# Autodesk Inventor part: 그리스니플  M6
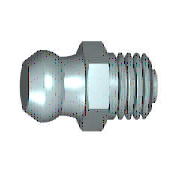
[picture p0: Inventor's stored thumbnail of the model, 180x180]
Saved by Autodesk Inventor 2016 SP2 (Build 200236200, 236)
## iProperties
IsCustomPart: 1
Created: 2012-02
Part Number: 그리스니플  M6
Material: 강철, 연강
Description: 그리스 니플에 대한 사양. 제I부: 버튼 머리 그리스 니플 유형 A
Document SubType Name: Modeling
Standard: IS 4009
Designer: mduedu
Standards Organization: IS
Language: ko-KR
Size Designation: M6 원추 짧은
Categories: <MemberInstance><Categories><Category DisplayName="기타 부품" InternalName="5aa15e00-363f-49f2-933f-16f664388e3f" Mnemonic="OTHER"><Category DisplayName="그리스 부속품" I
Density: 1 g/cm^3
Appearance: 강철
Author: mduedu
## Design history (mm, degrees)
sketch "스케치1"
  geometry: L1 (-9.8, 0)-(-9.8, 2.25); L2 (-9.8, 2.25)-(-8.055, 3.194); L3 (-9.8, 0)-(6.2, 0); L4 (6.2, 0)-(6.2, 1.5); L5 (6.2, 1.5)-(5.5, 1.5); L6 (5.5, 1.5)-(5.5, 3); L7 (5.5, 3)-(0, 3); L8 (-13, 0)-(9.4, 0) reference; L9 (0, -1.725)-(0, 10.35) reference; L10 (-3, 3.5)-(0, 3.5); L11 (0, 3.5)-(0, 3); A1 r 3.25 centre (-7.455, 0) between (-5.573, 2.65) and (-8.055, 3.194); A2 r 6 centre (-6.12, 8.625) between (-5.573, 2.65) and (-3, 3.5)
  constraints: 18 end point, 5 perpendicular, 4 point on circle, 2 centre point, 2 parallel, 2 point on line, 1 collinear, 1 vertical
  dimensions: "d0" = 16 distance between parallel lines of L1 L4 (= GL); "d1" = 5.3 diameter of A1.start L3 (= KGB2); "d2" = 0.7 distance between parallel lines of L4 L6 (= PHH); "d3" = 3 diameter of L5 L3 (= 0.5 x NND); "d4" = 6 diameter of L7 L3 (= NND); "d5" = 6.5 dimension on A1 L3 (= KR); "d6" = 4.5 diameter of L1.end L3 (= KGB1); "d7" = 6 radius of A2 (= RBN); "d11" = 7 diameter of L10.start L3 (= SW); "d14" = 3 distance of L10.start L10.end (= KOH); "d15" = 5.5 distance between parallel lines of L6 L11 (= NLG); "d61" = 8.05479 distance from line of L9 L2.end (computed from KGB1, KR, PHH, GL, NLG, VERS); "d62" = 7.45479 distance from line of L9 A1.centre (computed from NLG, GL, PHH, KR, KGB1)
revolve "본체" sketch "스케치1" stored, may be unused: angle "d25" = 90 deg
sketch "스케치2"
  geometry: L1 (2.021, 3.5)-(4.041, 0); L2 (4.041, 0)-(2.021, -3.5); L3 (2.021, -3.5)-(-2.021, -3.5); L4 (-2.021, -3.5)-(-4.041, 0); L5 (-4.041, 0)-(-2.021, 3.5); L6 (-2.021, 3.5)-(2.021, 3.5); C1 r 3.5 at (0, 0) reference; 1 further point
  constraints: 12 end point, 1 coincident, 1 horizontal, 1 tangent, 11 other
extrude "머리" join sketch "스케치2" distance "d17" = 3 (= KOH); taper "d18" = 0 deg
sketch "스케치3"
  geometry: L1 (2.687, 4.041)-(3, 4.041); L2 (3, 4.041)-(3, 3.5); L3 (3, 3.5)-(2.687, 4.041); L4 (0.313, 4.041)-(0, 4.041); L5 (0, 4.041)-(0, 3.5); L6 (0, 3.5)-(0.313, 4.041); L7 (3.6, 0)-(-0.6, 0) reference; L8 (0, 4.041)-(0, 2.021) reference; L9 (0, 4.041)-(3, 4.041) reference; L10 (3, 3.031)-(3, 4.041) reference
  constraints: 12 end point, 4 collinear, 3 perpendicular, 1 horizontal
  dimensions: "d19" = 3.5 distance from line of L5.end L7 (= 0.5 x SW); "d20" = 3.5 distance from line of L2.end L7 (= 0.5 x SW); "d21" = 30 deg angle of L6 L5; "d22" = 30 deg angle of L2 L3
revolve "모따기1" sketch "스케치3" stored, may be unused: angle "d56" = 90 deg
body "Solid1"
fillet "모깎기1" dims "d8" = 0.2 (= RR)
feature "스레드1" dims "d9" = 4.88655 (= NLG - GAL), "d10" = 0
chamfer "모따기2" distance "d23" = 0.61345 (= -0.5 x GD1 + 0.5 x NND); stored, may be unused: angle "d24" = 45 deg, second distance "d59" = 0.61345 (= -0.5 x GD1 + 0.5 x NND)
other parameters: "NLG" = 5.5 [user parameter; used in 4 equation terms], "GL" = 16 [user parameter; used in 3 equation terms], "NND" = 6 [user parameter; used in 4 equation terms], "KGB1" = 4.5 [user parameter; used in 3 equation terms], "KGB2" = 5.3 [user parameter; used in 1 equation term], "VERS" = 0.6 [user parameter; used in 1 equation term], "KR" = 6.5 [user parameter; used in 3 equation terms], "RBN" = 6 [user parameter; used in 1 equation term], "SW" = 7 [user parameter; used in 3 equation terms], "KOH" = 3 [user parameter; used in 2 equation terms], "GAL" = 0.61345 (= 0.61345 x PTC) [user parameter; used in 1 equation term], "FAWI" = 45 deg [user parameter], "PHH" = 0.7 [user parameter; used in 3 equation terms], "GD1" = 4.7731 (= THREADDIA - 1.2269 x PTC) [user parameter; used in 2 equation terms], "RR" = 0.2 [user parameter; used in 1 equation term], "d12" = 0, "d13" = 0, "GUL" = 0.61345 (= 0.61345 x PTC) [user parameter], "DULO" = 1.5 [user parameter], "PTC" = 1 [user parameter; used in 4 equation terms], "GEL" = 5.5 [user parameter], "THREADDIA" = 6 [user parameter; used in 1 equation term], "TOA" = 30 deg [user parameter]
